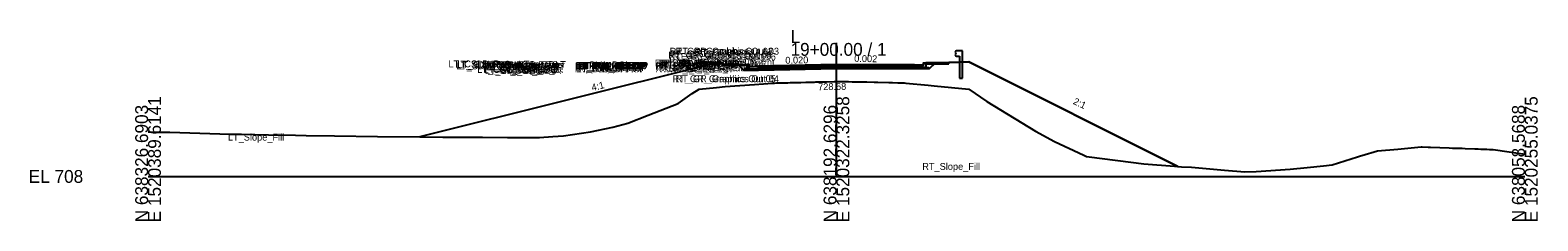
# Model space of a CAD drawing. Extents: x -26 to 3903, y -10 to 9531.
# Drawn here: x -25.7 to 302.8, y 8990.3 to 9031.9 of the extents above; entities that cross this region are included whole.
import ezdxf

# ---------------------------------------------------------------- set-up
doc = ezdxf.new("R2010")
doc.units = 0
for name, color, linetype in [('Default', 7, 'Continuous'), ('Exist Cross Section Cell', 7, 'Continuous'), ('Exist XS Center Line Elevation Label', 7, 'Continuous'), ('Exist XS Ground Line', 7, 'Continuous'), ('Old_Level_63', 7, 'Continuous'), ('Prop CMT Conc Surface', 7, 'Continuous'), ('Prop CMT Guardrail Graphics', 7, 'Continuous'), ('Prop CMT Pvmt Course 1', 7, 'Continuous'), ('Prop CMT Pvmt Course 1 CG', 7, 'Continuous'), ('Prop CMT Pvmt Course 2', 7, 'Continuous'), ('Prop CMT Pvmt Course 3', 7, 'Continuous'), ('Prop CMT Pvmt Surface', 7, 'Continuous'), ('Prop CMT Slope Grass', 7, 'Continuous'), ('Prop CMT Subgrade Earthwork', 7, 'Continuous'), ('Prop XS Earthwork Shape', 7, 'Continuous'), ('Prop XS Finish Grade Concrete', 7, 'Continuous'), ('Prop XS SE Text', 7, 'Continuous'), ('Prop XS Side Slope Text', 7, 'Continuous')]:
    doc.layers.add(name, color=color, linetype=linetype)

msp = doc.modelspace()

# ---------------------------------------------------------------- linework, layer by layer
at = {"layer": 'Exist Cross Section Cell'}
for p, q in [((150, 9000), (150, 9029.11)), ((0, 9000), (150, 9000)), ((150, 9000), (300, 9000))]:
    msp.add_line(p, q, dxfattribs=at)
at = {"layer": 'Exist XS Ground Line'}
msp.add_lwpolyline([(0, 9009.7), (1.22, 9009.69), (4.72, 9009.64), (17.82, 9009.25), (20.34, 9009.21), (26.23, 9009.09), (32.13, 9008.97), (34.45, 9008.94), (40.59, 9008.86), (49.96, 9008.71), (59.29, 9008.63), (64.25, 9008.59), (66.92, 9008.57), (72.87, 9008.57), (78.35, 9008.49), (82.56, 9008.49), (85.3, 9008.49), (88.22, 9008.69), (90.53, 9008.86), (96.39, 9009.73), (101.27, 9010.74), (104.56, 9011.6), (108.97, 9013.33), (115.49, 9015.89), (118.56, 9018.06), (120.09, 9019.06), (123.85, 9019.43), (125.77, 9019.59), (132.13, 9020.07), (136.09, 9020.35), (136.48, 9020.37), (136.96, 9020.38), (138.97, 9020.43), (139.44, 9020.44), (139.95, 9020.46), (142.24, 9020.51), (143.34, 9020.54), (145.04, 9020.58), (145.2, 9020.59), (145.51, 9020.6), (147.82, 9020.64), (149.52, 9020.67), (149.97, 9020.68), (150.52, 9020.67), (151.07, 9020.67), (152.63, 9020.67), (153.4, 9020.66), (155.74, 9020.62), (156.19, 9020.62), (156.64, 9020.61), (158.2, 9020.58), (158.99, 9020.56), (161.39, 9020.5), (161.79, 9020.49), (161.92, 9020.49), (162.21, 9020.49), (163.36, 9020.45), (164.29, 9020.41), (164.79, 9020.39), (165.14, 9020.37), (169.96, 9019.88), (170.66, 9019.82), (171.28, 9019.73), (178.87, 9019.02), (182.74, 9016.34), (193.35, 9009.87), (197.51, 9007.59), (203.9, 9004.63), (204.5, 9004.35), (205.09, 9004.28), (216.96, 9002.78), (223.64, 9002.24), (225.19, 9002.13), (227.4, 9002.03), (234.56, 9001.34), (238.99, 9000.97), (241.49, 9001.11), (248.86, 9001.61), (252.57, 9001.96), (256.12, 9002.32), (258.04, 9002.53), (263.56, 9004.31), (264.16, 9004.48), (264.5, 9004.57), (267.92, 9005.56), (272.33, 9005.98), (277.39, 9006.43), (277.41, 9006.43), (277.63, 9006.42), (278.93, 9006.36), (279.45, 9006.35), (281.48, 9006.29), (283.52, 9006.22), (284.25, 9006.2), (284.5, 9006.19), (285, 9006.18), (286.35, 9006.14), (287.02, 9006.12), (289.1, 9006.03), (289.84, 9006.01), (290.43, 9005.98), (291.59, 9005.95), (291.75, 9005.93), (292.29, 9005.9), (293.09, 9005.88), (299.58, 9004.94), (300, 9004.87)], dxfattribs=at)
at = {"layer": 'Old_Level_63'}
for p, q in [((131, 9023.92), (131, 9024.42)), ((133, 9024.04), (131, 9023.92)), ((169, 9024.27), (167, 9024.35)), ((169, 9024.77), (169, 9024.27))]:
    msp.add_line(p, q, dxfattribs=at)
for points in [[(174.5, 9024.87), (169.5, 9024.77)], [(174.5, 9024.55), (174.5, 9024.87)], [(125.5, 9024.19), (125.5, 9024.52)], [(130.5, 9024.09), (125.5, 9024.19)], [(130.5, 9024.42), (130.5, 9023.41), (133, 9023.46)], [(133, 9023.46), (133, 9024.04)], [(169.5, 9024.77), (169.5, 9023.77), (167, 9023.77)], [(167, 9023.77), (167, 9024.35)], [(169.5, 9024.46), (174.5, 9024.55)]]:
    msp.add_lwpolyline(points, dxfattribs=at)
at = {"layer": 'Prop CMT Conc Surface'}
for points in [[(119.5, 9024.72), (124.5, 9024.82)], [(169.5, 9024.72), (174.5, 9024.82)], [(80.5, 9024.37), (75.5, 9024.47)], [(81, 9023.86), (81, 9024.36), (80.5, 9024.36)], [(83, 9023.98), (81, 9023.86)], [(117, 9024.29), (119, 9024.21)], [(119, 9024.21), (119, 9024.71), (119.5, 9024.71)], [(130.5, 9024.37), (125.5, 9024.47)], [(131, 9023.86), (131, 9024.36), (130.5, 9024.36)], [(133, 9023.98), (131, 9023.86)], [(167, 9024.29), (169, 9024.21)], [(169, 9024.21), (169, 9024.71), (169.5, 9024.71)]]:
    msp.add_lwpolyline(points, dxfattribs=at)
at = {"layer": 'Prop CMT Guardrail Graphics'}
for points in [[(177.45, 9027.42), (176.12, 9027.42), (175.85, 9027.13)], [(175.85, 9027.13), (176.12, 9026.84)], [(176.12, 9026.84), (175.85, 9026.55)], [(175.85, 9026.55), (176.12, 9026.25), (176.79, 9026.25)], [(176.79, 9026.25), (176.79, 9021.42)], [(177.45, 9021.42), (177.45, 9027.42)], [(176.79, 9021.42), (177.45, 9021.42)]]:
    msp.add_lwpolyline(points, dxfattribs=at)
at = {"layer": 'Prop CMT Pvmt Course 1'}
for q in [(133, 9024.04), (167, 9024.35)]:
    msp.add_line((150, 9024.38), q, dxfattribs=at)
for points in [[(133, 9023.79), (150, 9024.13)], [(133, 9024.04), (133, 9023.79)], [(150, 9024.13), (150, 9024.38)], [(150, 9024.13), (150, 9024.38)], [(167, 9024.1), (150, 9024.13)], [(167, 9024.35), (167, 9024.1)]]:
    msp.add_lwpolyline(points, dxfattribs=at)
msp.add_lwpolyline([(150, 9024.13), (150, 9024.26), (150, 9024.26), (150, 9024.13)], close=True, dxfattribs=at)
msp.add_lwpolyline([(150, 9024.13), (150, 9024.26), (150, 9024.26), (150, 9024.13)], close=True, dxfattribs=at)
at = {"layer": 'Prop CMT Pvmt Course 1 CG'}
for points in [[(133, 9023.46), (130, 9023.4), (129.74, 9023.15)], [(129.74, 9023.15), (133, 9023.21)], [(133, 9023.21), (133, 9023.46)], [(167, 9023.77), (170, 9023.77), (170.25, 9023.52)], [(167, 9023.52), (167, 9023.77)], [(170.25, 9023.52), (167, 9023.52)]]:
    msp.add_lwpolyline(points, dxfattribs=at)
at = {"layer": 'Prop CMT Pvmt Course 2'}
for points in [[(150, 9024.13), (133, 9023.79)], [(133, 9023.46), (150, 9023.8)], [(133, 9023.79), (133, 9023.46)], [(150, 9023.8), (150, 9024.13)], [(150, 9023.8), (150, 9024.13)], [(150, 9024.13), (167, 9024.1)], [(167, 9023.77), (150, 9023.8)], [(167, 9024.1), (167, 9023.77)]]:
    msp.add_lwpolyline(points, dxfattribs=at)
at = {"layer": 'Prop CMT Pvmt Course 3'}
for points in [[(150, 9023.8), (133, 9023.46)], [(133, 9023.21), (150, 9023.55)], [(133, 9023.46), (133, 9023.21)], [(150, 9023.55), (150, 9023.8)], [(150, 9023.8), (167, 9023.77)], [(150, 9023.55), (150, 9023.8)], [(167, 9023.52), (150, 9023.55)], [(167, 9023.77), (167, 9023.52)]]:
    msp.add_lwpolyline(points, dxfattribs=at)
at = {"layer": 'Prop CMT Pvmt Surface'}
for p, q in [((150, 9024.38), (133, 9024.04)), ((167, 9024.35), (150, 9024.38))]:
    msp.add_line(p, q, dxfattribs=at)
for points in [[(150, 9024.38), (133, 9024.04)], [(150, 9024.38), (167, 9024.35)]]:
    msp.add_lwpolyline(points, dxfattribs=at)
at = {"layer": 'Prop CMT Slope Grass'}
for p, q in [((178.85, 9024.96), (224.39, 9002.19)), ((123, 9024.57), (59.23, 9008.63))]:
    msp.add_line(p, q, dxfattribs=at)
for points in [[(174.5, 9024.87), (178.85, 9024.96)], [(125.5, 9024.52), (123, 9024.57)]]:
    msp.add_lwpolyline(points, dxfattribs=at)
at = {"layer": 'Prop CMT Subgrade Earthwork'}
for points in [[(167, 9023.52), (170.25, 9023.52), (171.55, 9024.81)], [(133, 9023.21), (129.74, 9023.15), (128.43, 9024.47)], [(150, 9023.55), (133, 9023.21)], [(150, 9023.55), (167, 9023.52)]]:
    msp.add_lwpolyline(points, dxfattribs=at)
at = {"layer": 'Prop XS Earthwork Shape'}
for points in [[(161.92, 9020.49), (162.21, 9020.49), (163.36, 9020.45), (164.29, 9020.41), (164.79, 9020.39), (165.14, 9020.37), (169.96, 9019.88), (170.66, 9019.82), (171.28, 9019.73), (178.87, 9019.02), (182.74, 9016.34), (193.35, 9009.87), (197.51, 9007.59), (203.9, 9004.63), (204.5, 9004.35), (205.09, 9004.28), (216.96, 9002.78), (223.64, 9002.24), (224.39, 9002.19), (178.85, 9024.96), (174.5, 9024.82), (171.49, 9024.75), (170.25, 9023.52), (167, 9023.52), (150, 9023.55), (133, 9023.21), (129.74, 9023.15), (128.48, 9024.41), (125.5, 9024.47), (123, 9024.57), (59.23, 9008.63), (64.25, 9008.59), (66.92, 9008.57), (72.87, 9008.57), (78.35, 9008.49), (82.56, 9008.49), (85.3, 9008.49), (88.22, 9008.69), (90.53, 9008.86), (96.39, 9009.73), (101.27, 9010.74), (104.56, 9011.6), (108.97, 9013.33), (115.49, 9015.89), (118.56, 9018.06), (120.09, 9019.06), (123.85, 9019.43), (125.77, 9019.59), (132.13, 9020.07), (136.09, 9020.35), (136.48, 9020.37), (136.96, 9020.38), (138.97, 9020.43), (139.44, 9020.44), (139.95, 9020.46), (142.24, 9020.51), (143.34, 9020.54), (145.04, 9020.58), (145.2, 9020.59), (145.51, 9020.6), (147.82, 9020.64), (149.52, 9020.67), (149.97, 9020.68), (150.52, 9020.67), (151.07, 9020.67), (152.63, 9020.67), (153.4, 9020.66), (155.74, 9020.62), (156.19, 9020.62), (156.64, 9020.61), (158.2, 9020.58), (158.99, 9020.56), (161.39, 9020.5), (161.79, 9020.49)], [(88.22, 9008.69), (90.53, 9008.86), (96.39, 9009.73), (101.27, 9010.74), (104.56, 9011.6), (108.97, 9013.33), (115.49, 9015.89), (118.56, 9018.06), (120.09, 9019.06), (123.85, 9019.43), (125.77, 9019.59), (132.13, 9020.07), (136.09, 9020.35), (136.48, 9020.37), (136.96, 9020.38), (138.97, 9020.43), (139.44, 9020.44), (139.95, 9020.46), (142.24, 9020.51), (143.34, 9020.54), (145.04, 9020.58), (145.2, 9020.59), (145.51, 9020.6), (147.82, 9020.64), (149.52, 9020.67), (149.97, 9020.68), (150.52, 9020.67), (151.07, 9020.67), (152.63, 9020.67), (153.4, 9020.66), (155.74, 9020.62), (156.19, 9020.62), (156.64, 9020.61), (158.2, 9020.58), (158.99, 9020.56), (161.39, 9020.5), (161.79, 9020.49), (161.92, 9020.49), (162.21, 9020.49), (163.36, 9020.45), (164.29, 9020.41), (164.79, 9020.39), (165.14, 9020.37), (169.96, 9019.88), (170.66, 9019.82), (171.28, 9019.73), (178.87, 9019.02), (182.74, 9016.34), (193.35, 9009.87), (197.51, 9007.59), (203.9, 9004.63), (204.5, 9004.35), (205.09, 9004.28), (216.96, 9002.78), (223.64, 9002.24), (224.39, 9002.19), (178.85, 9024.96), (174.5, 9024.82), (171.49, 9024.75), (170.25, 9023.52), (167, 9023.52), (150, 9023.55), (133, 9023.21), (129.74, 9023.15), (128.48, 9024.41), (125.5, 9024.47), (123, 9024.57), (59.23, 9008.63), (64.25, 9008.59), (66.92, 9008.57), (72.87, 9008.57), (78.35, 9008.49), (82.56, 9008.49), (85.3, 9008.49)]]:
    msp.add_lwpolyline(points, close=True, dxfattribs=at)
at = {"layer": 'Prop XS Finish Grade Concrete'}
for points in [[(174.5, 9024.87), (169.5, 9024.77)], [(125.5, 9024.52), (130.5, 9024.42)], [(133, 9024.04), (131, 9023.92), (131, 9024.42), (130.5, 9024.42)], [(167, 9024.35), (169, 9024.27), (169, 9024.77), (169.5, 9024.77)]]:
    msp.add_lwpolyline(points, dxfattribs=at)

# ---------------------------------------------------------------- texts
at = {"layer": 'Default'}
msp.add_text('-', height=0.0001, dxfattribs=at).set_placement((0, 9000))
at = {"layer": 'Exist Cross Section Cell'}
for s, p in [('L', (140, 9029.11)), ('19+00.00 / 1', (140, 9026.31)), ('EL 708', (-26, 8998.6))]:
    msp.add_text(s, height=2.8, dxfattribs=at).set_placement(p)
for s, p in [('N 638326.6903', (0, 8990)), ('E 1520389.6141', (2.8, 8990)), ('N 638192.6296', (150, 8990)), ('E 1520322.3258', (152.8, 8990)), ('N 638058.5688', (300, 8990)), ('E 1520255.0375', (302.8, 8990))]:
    msp.add_text(s, height=2.8, rotation=90, dxfattribs=at).set_placement(p)
at = {"layer": 'Exist XS Center Line Elevation Label'}
msp.add_text('728.68', height=1.5, rotation=0.8401, dxfattribs=at).set_placement((146.01, 9018.8))
at = {"layer": 'Prop CMT Conc Surface'}
for s, p in [('RT_GR_Graphics Out 02', (113.66, 9026.56)), ('RT_GR_Graphics Out 03', (114.97, 9026.56)), ('LT_CSLP_Pnt', (65.45, 9023.8)), ('LT_SDWK_Out_Top', (66.94, 9023.72)), ('LT_SDWK_Out_Bot', (67.12, 9023.39)), ('LT_Sub_Trench_Out_DLT', (67.4, 9023.65)), ('LT_SDWK_In_Top', (72.8, 9023.62)), ('LT_CG_Top_BOC', (72.86, 9023.61)), ('LT_SDWK_In_Bot', (72.99, 9023.29)), ('LT_CG_Top_Face', (73.38, 9023.61)), ('RT_PV2_OEEOP', (93, 9023.32)), ('LT_PV2_OEEOP', (93.09, 9023.32)), ('RT_PV1_OEEOP', (93.18, 9023.45)), ('LT_PV1_OEEOP', (93.27, 9023.45)), ('RT_PV2_IEEOP', (93.57, 9023.32)), ('LT_PV2_IEEOP', (93.66, 9023.32)), ('RT_PV1_IEEOP', (93.75, 9023.45)), ('LT_PV1_IEEOP', (93.84, 9023.45)), ('PV2_PGL', (96.03, 9023.32)), ('PV1_PGL', (96.2, 9023.57)), ('RT_Sub_Trench_Out_DLT', (110.43, 9024)), ('RT_PV2_OEOT', (110.53, 9023.29)), ('RT_PV1_OEOT', (110.71, 9023.54)), ('RT_CG_Top_Face', (111.29, 9023.96)), ('RT_CG_Top_Gut', (111.69, 9023.46)), ('RT_SDWK_In_Top', (111.71, 9023.97)), ('RT_CG_Top_BOC', (111.77, 9023.96)), ('RT_SDWK_In_Bot', (111.9, 9023.64)), ('RT_GR_Graphics Out 08', (113.35, 9025.68)), ('RT_GR_Graphics Out 07', (113.6, 9025.39)), ('RT_GR_Graphics Out 09', (113.62, 9025.97)), ('RT_GR_Graphics Out 06', (114.29, 9025.39)), ('RT_SDWK_Out_Top', (115.85, 9024.07)), ('RT_SDWK_Out_Bot', (116.03, 9023.74)), ('RT_GR_Out', (119.2, 9026.26)), ('RT_CSLP_Pnt', (123.36, 9024.15)), ('LT_CG1_Shelf_Out', (71.73, 9022.59)), ('LT_CG_Bot_BOC', (73.07, 9022.6)), ('LT_Sub_OEOP', (73.39, 9022.33)), ('LT_CG_Top_Gut', (73.78, 9023.11)), ('LT_PV2_OEOT', (76.62, 9022.98)), ('LT_PV3_OEOT', (76.62, 9022.65)), ('LT_Sub_OEOT', (76.65, 9022.4)), ('LT_PV1_OEOT', (76.8, 9023.23)), ('LT_CG_Bot_IE', (76.88, 9022.65)), ('RT_PV3_OEEOP', (93, 9022.99)), ('RT_Sub_OEEOP', (93.04, 9022.74)), ('LT_PV3_OEEOP', (93.09, 9022.99)), ('LT_Sub_OEEOP', (93.12, 9022.74)), ('RT_PV3_OEOT', (110.53, 9022.96)), ('RT_Sub_OEOT', (110.56, 9022.71)), ('RT_CG_Bot_IE', (110.79, 9022.96)), ('RT_CG1_Shelf_Out', (111.64, 9022.95)), ('RT_CG_Bot_BOC', (111.98, 9022.96)), ('RT_Sub_OEOP', (113.81, 9022.7)), ('RT_GR_Graphics Out 05', (114.29, 9020.56)), ('RT_GR_Graphics Out 04', (114.95, 9020.56)), ('LT_Slope_Fill', (17.4, 9007.82)), ('RT_Slope_Fill', (168.7, 9001.43))]:
    msp.add_text(s, height=1.5, dxfattribs=at).set_placement(p)
at = {"layer": 'Prop XS SE Text'}
for s, rotation, p in [('0.020', 1.1458, (138.87, 9024.58)), ('0.002', 358.8542, (153.86, 9025))]:
    msp.add_text(s, height=1.5, rotation=rotation, dxfattribs=at).set_placement(p)
at = {"layer": 'Prop XS Side Slope Text'}
for s, rotation, p in [('4:1', 14.0362, (96.82, 9018.61)), ('2:1', 334.8977, (201.44, 9015.86))]:
    msp.add_text(s, height=1.5, rotation=rotation, dxfattribs=at).set_placement(p)

doc.saveas('drawing.dxf')
